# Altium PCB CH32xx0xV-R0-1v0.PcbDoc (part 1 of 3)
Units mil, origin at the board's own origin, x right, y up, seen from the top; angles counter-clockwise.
Board outline 3661.42 x 3267.72 mil, 2 copper layers (Top Layer, Bottom Layer); 68 components, 119 nets, 417 pads, 746 vias.
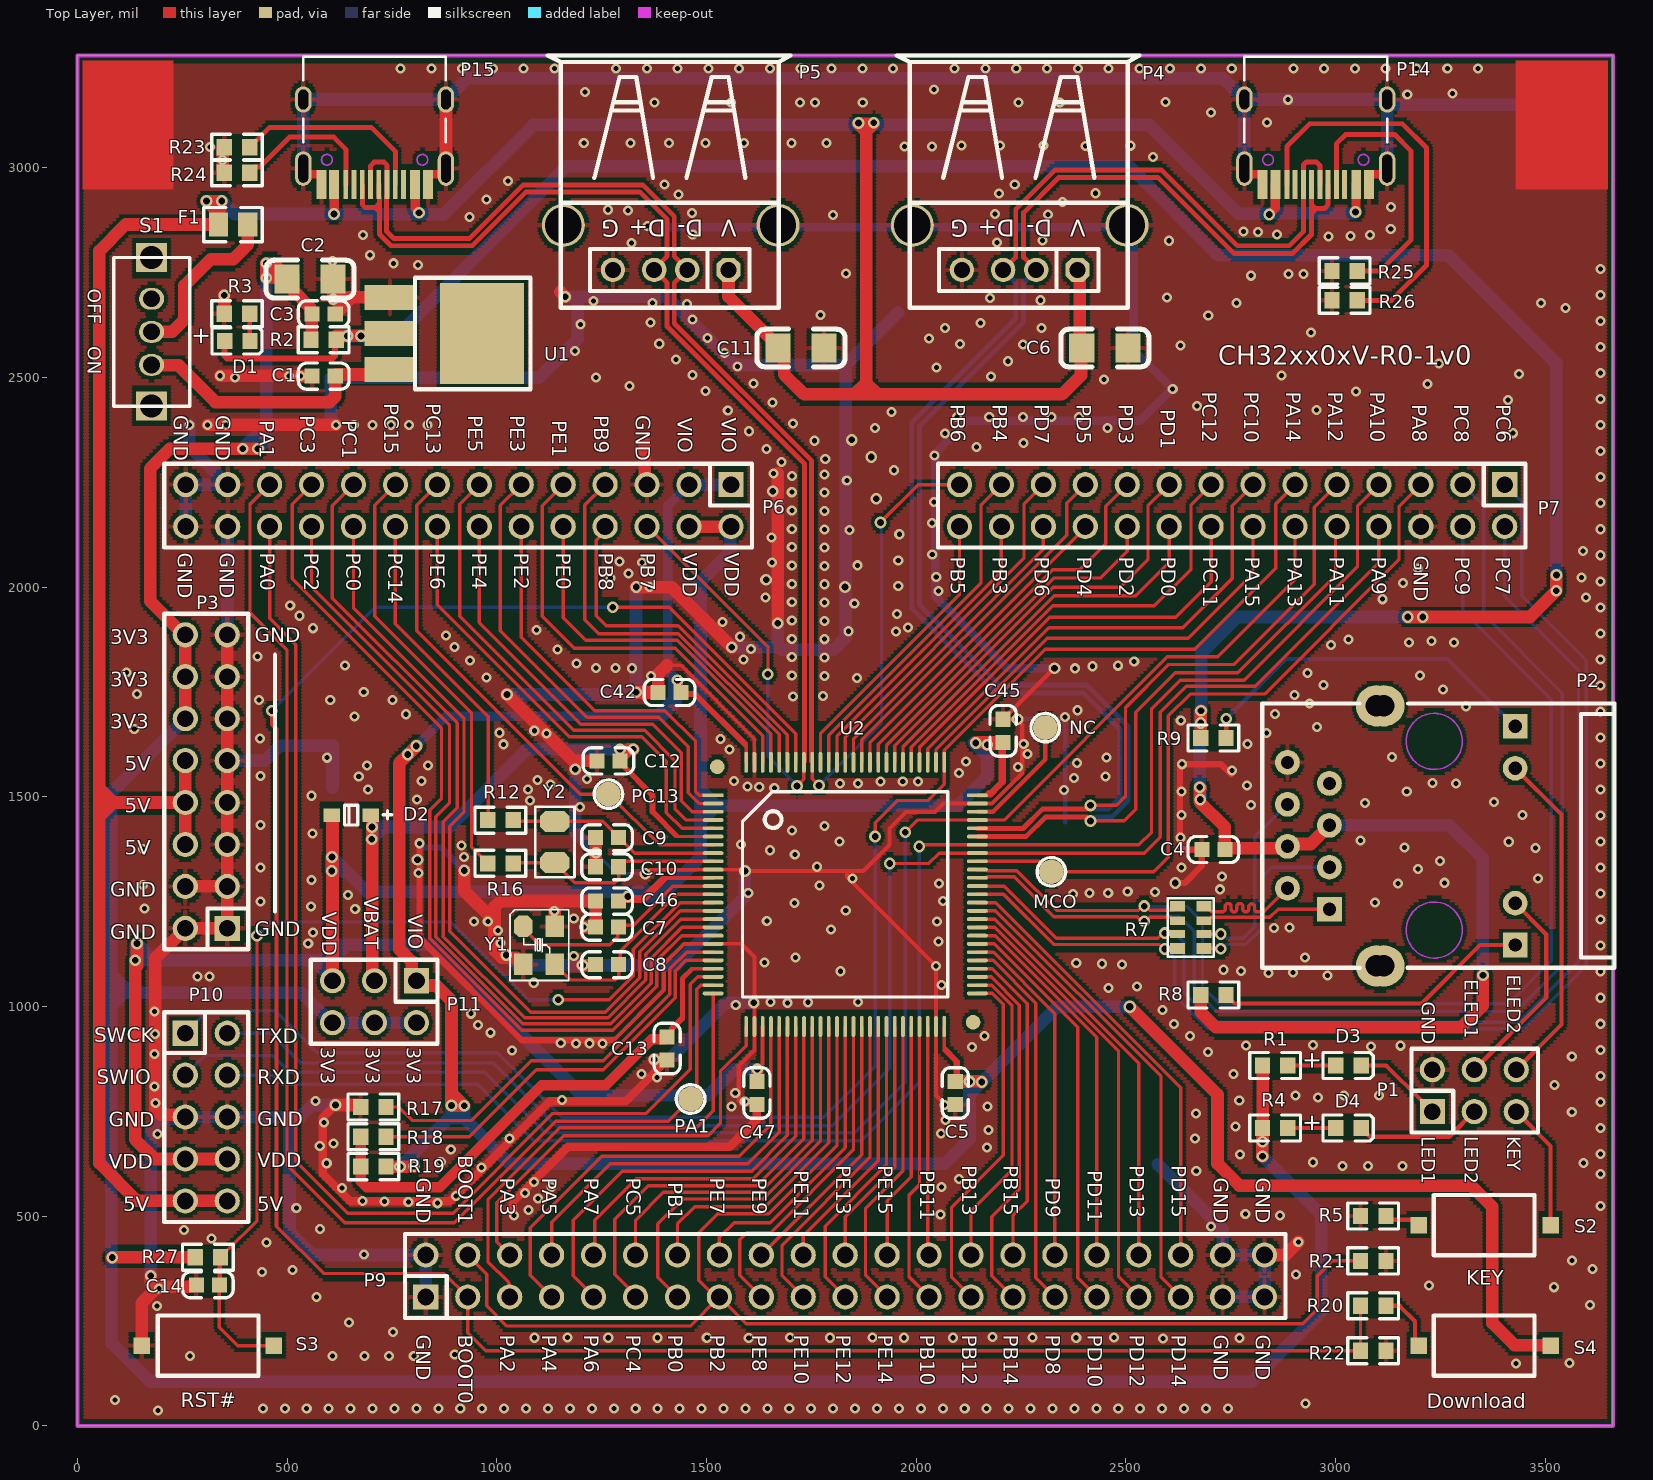
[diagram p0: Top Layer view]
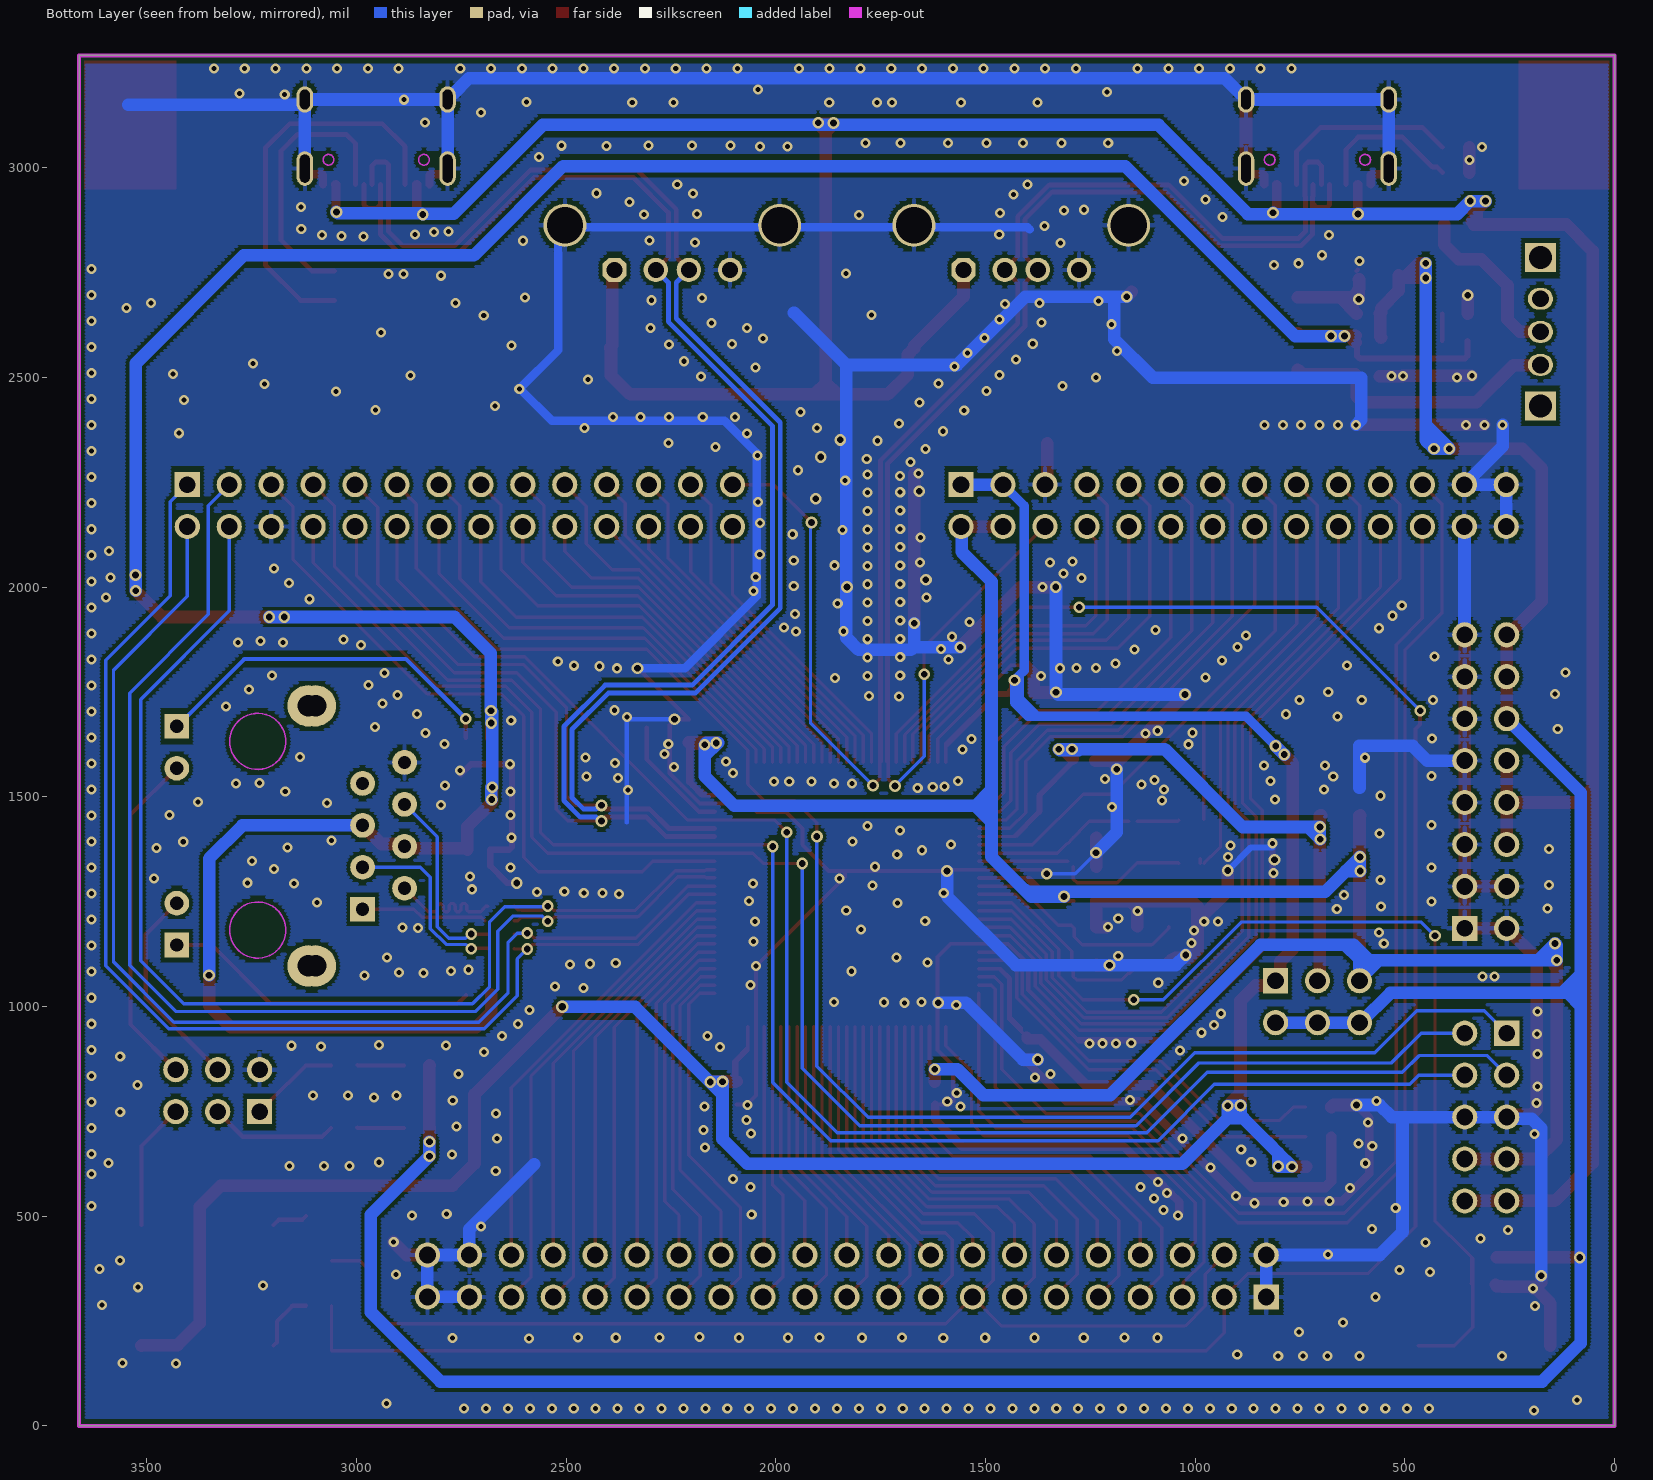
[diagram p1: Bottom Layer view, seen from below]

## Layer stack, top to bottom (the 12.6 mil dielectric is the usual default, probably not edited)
Top Solder: solder mask 0.4, Solder Resist, Dk 3.5
Top Layer: signal copper 1.4
Dielectric 1: dielectric 12.6, FR-4, Dk 4.8
Bottom Layer: signal copper 1.4
Bottom Solder: solder mask 0.4, Solder Resist, Dk 3.5

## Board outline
0,0 0,3267.72 3661.42,3267.72 3661.42,0

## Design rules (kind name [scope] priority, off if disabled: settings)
Clearance Clearance_1 [InPolygon] p1: gap=8 ignorepadtopadclearanceinfootprint=FALSE
Clearance [All] p2: gap=5 ignorepadtopadclearanceinfootprint=FALSE
ComponentClearance [All] p1 off: gap=10 collisioncheckmode=3 verticalgap=10 showdistances=FALSE
DiffPairsRouting [All] p1: maxlimit=10 minlimit=5 mostfreqgap=7 toplayer_minwidth=8 toplayer_maxwidth=15 toplayer_prefwidth=8 bottomlayer_minwidth=8 bottomlayer_maxwidth=15 bottomlayer_prefwidth=8 maxuncoupledlength=500
MinimumSolderMaskSliver [All] p1 off: minsoldermaskwidth=10
PolygonConnect PolygonConnect_1 [IsVia] p1: connectstyle=Direct reliefconductorwidth=10 reliefentries=4 polygonreliefangle="90 Angle" airgapwidth=10
PolygonConnect [All] p2: connectstyle=Relief reliefconductorwidth=10 reliefentries=4 polygonreliefangle="90 Angle" airgapwidth=10
RoutingVias [All] p1: holewidth=16 width=28 viastyle="Through Hole" minholewidth=12 minwidth=24 maxholewidth=28 maxwidth=50
SilkToSilkClearance [All] p1 off: silktosilkclearance=10
SilkToSolderMaskClearance [IsPad] p1 off: minsilkscreentomaskgap=10 clearancetoexposedcopper=TRUE
SolderMaskExpansion [All] p1: expansion=4 istentingtop=FALSE
Width [All] p1: maxlimit=100 minlimit=6 preferedwidth=10
25 further rules are at their usual default settings.

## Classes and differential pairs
differential pair ERX1: +ERXP1 -ERXN1

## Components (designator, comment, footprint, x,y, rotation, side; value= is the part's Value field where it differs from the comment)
C1 "0.1uF" 0603_C 614.71,2503.21 r180 top
C2 "10uF" 3216_C 499.71,2734.59 r180 top
C3 "0.1uF" 0603_C 559.72,2651.67 r0 top
C4 "1uF" 0603_C 2681.03,1374.36 r0 top
C5 "0.1uF" 0603_C 2093.21,821.36 r270 top
C6 "10uF" 3216_C 2394.73,2570.1 r180 top
C7 "22pF" 0603_C 1235.4,1189.11 r0 top
C8 "22pF" 0603_C 1235.4,1099.73 r0 top
C9 "12pF" 0603_C 1235.4,1402.61 r0 top
C10 "12pF" 0603_C 1235.4,1333.23 r0 top
C11 "10uF" 3216_C 1670.08,2570.1 r180 top
C12 "0.1uF" 0603_C 1238.69,1585.69 r0 top
C13 "0.1uF" 0603_C 1406.03,927.4 r270 top
C14 "0.1uF" 0603_C 283.44,336.36 r0 top
C42 "0.1uF" 0603_C 1384.49,1748.68 r0 top
C45 "0.1uF" 0603_C 2207.3,1629.96 r90 top
C46 "0.1uF" 0603_C 1290.39,1251.48 r180 top
C47 "0.1uF" 0603_C 1620.21,766.37 r90 top
D1 "RED" 0603+ 350.83,2586.93 r0 top
D2 "B0520WS" SOD-323 699.12,1456.36 r180 top
D3 "BLUE" 0603+ 3000.21,859.36 r0 top
D4 "RED" 0603+ 3000.21,710.36 r0 top
F1 "500mA" 0805 336.17,2864.6 r0 top
MCO "Testpoint" TESTPOINT1 2322.21,1321.36 r0 top
NC "Testpoint" TESTPOINT1 2307.69,1664.95 r0 top
P1 "IO" IDC6-2.54mm 3230.77,749.27 r0 top
P2 "HR911105A" HR911105A 2985.22,1231.99 r90 top
P3 "HEADER 8x2" IDC16-2.54mm 357.21,1186.36 r180 top
P4 "USBFS" USBAF 2384.59,2756.36 r180 top
P5 "USBHS" USBAF 1552.42,2756.36 r180 top
P6 "HEADER 14x2" IDC28-2.54MM 1558.21,2244.36 r270 top
P7 "HEADER 14x2" IDC28-2.54MM 3403.21,2244.36 r270 top
P9 "HEADER 21x2" IDC42-2.54MM 830.71,307.44 r90 top
P10 "LINK" IDC10-2.54mm 257.21,536.36 r0 top
P11 "HEADER 3x2" IDC6-2.54mm 808.21,1061.36 r180 top
P14 "USBFS" TYPE-C-Receptacle-2.0 2952.78,2959.96 r180 top
P15 "USBHS" TYPE-C-Receptacle-2.0 708.64,2959.96 r180 top
PA1 "Testpoint" TESTPOINT1 1462.18,779.41 r0 top
PC13 "Testpoint" TESTPOINT1 1266.21,1506.36 r0 top
R1 "1K" 0603 2825.58,859.36 r0 top
R2 "0R" 0603 556.9,2589.82 r0 top
R3 "1K" 0603 410.77,2651.66 r180 top
R4 "1K" 0603 2825.58,710.36 r0 top
R5 "10K" 0603 3059.47,500.58 r0 top
R7 "0Ω" RCA-8P4R-0603 2654.91,1188.5 r270 top
R8 "1K" 0603 2678.21,1027.36 r0 top
R9 "1K" 0603 2678.21,1640.36 r0 top
R12 "NC(0R)" 0603 978.21,1444.36 r0 top
R16 "NC(0R)" 0603 978.21,1341.36 r0 top
R17 "0R" 0603 675.15,760.26 r0 top
R18 "0R" 0603 675.15,689.26 r0 top
R19 "0R" 0603 735.78,618.26 r180 top
R20 "1K" 0603 3059.47,286.28 r0 top value=10K
R21 "10K" 0603 3059.47,393.43 r0 top
R22 "10K" 0603 3059.47,179.13 r0 top
R23 "NC(5.1K)" 0603 410.77,3048.82 r180 top
R24 "5.1K" 0603 410.77,2988 r180 top
R25 "5.1K" 0603 3051.97,2754.06 r180 top
R26 "5.1K" 0603 3051.97,2683.9 r180 top
R27 "10K" 0603 341.25,402.06 r180 top
S1 "SW SPDT" KEY2 176.66,2608.68 r90 top
S2 "KEY" SMD_6.1x3.65x2.5mm-KEY 3512.71,478.75 r180 top
S3 "RST#" SMD_6.1x3.65x2.5mm-KEY 153.21,191.36 r0 top
S4 "Download" SMD_6.1x3.65x2.5mm-KEY 3512.71,191.36 r180 top
U1 "1117-3.3V" SOT-223 744.97,2690.71 r270 top
U2 "CH32F207V" LQFP100 1515.75,1503.62 r270 top
Y1 "8MHz" XT3225 1063.21,1190.91 r270 top
Y2 "32768Hz" FC-135 1138.21,1441.36 r270 top

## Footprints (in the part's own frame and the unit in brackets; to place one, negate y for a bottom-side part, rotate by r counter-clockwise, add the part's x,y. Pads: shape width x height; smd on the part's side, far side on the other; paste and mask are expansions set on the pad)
0603 [mm]
  rect 0.93x0.98 smd: 1(0,0) 2(1.54,0)
  silkscreen extent -0.76,-0.79 2.3,0.79
0603+ [mm]
  rect 0.93x0.98 smd: 1(0,0) 2(1.54,0)
  silkscreen extent -0.76,-0.79 2.27,0.79
0603_C [mil]
  rect 36x36 smd: 1(0,0) 2(55,0)
  silkscreen extent -33,-31 88,31
0805 [mm]
  rect 1.16x1.47 smd: 1(0,0) 2(1.78,0)
  silkscreen extent -0.88,-1.04 2.66,1.03
3216_C [mil]
  rect 60x70 smd: 1(0,0) 2(-110,0)
  silkscreen extent -160,-45 50,45
FC-135 [mil]
  oct 50x70 smd: 1(0,0) 2(98.43,0)
  silkscreen extent -35,-47 133,47
HR911105A [mm]
  rect 1.5x1.5 hole 0.8: 1(0,0) 9(-2.175,-11.252) 12(11.075,-11.252)
  round 1.5 hole 0.8: 2(1.27,2.54) 3(2.54,0) 4(3.81,2.54) 5(5.08,0) 6(6.35,2.54) 7(7.62,0) 8(8.89,2.54) 10(0.365,-11.252) 11(8.535,-11.252)
  round 2.5 hole 1.3: ""(-3.43,-2.852) ""(-3.43,-3.3) ""(12.32,-3.3) ""(12.32,-2.852)
  Keep-Out Layer circle w0.1: c10.165,-6.352 r1.7
  Keep-Out Layer circle w0.1: c-1.265,-6.352 r1.7
  silkscreen extent -3.55,-17.27 12.45,4.06
IDC6-2.54mm [mil]
  rect 60x60 hole 40: 1(0,0)
  round 60 hole 40: 2(0,100) 3(100,0) 4(100,100) 5(200,0) 6(200,100)
  silkscreen extent -50,-50 252,150
IDC10-2.54mm [mil]
  rect 60x60 hole 40: 1(0,400)
  round 60 hole 40: 2(100,400) 3(0,300) 4(100,300) 5(0,200) 6(100,200) 7(0,100) 8(100,100) 9(0,0) 10(100,0)
  silkscreen extent -50,-50 150,450
IDC16-2.54mm [mil]
  rect 60x60 hole 40: 1(0,0)
  round 60 hole 40: 2(100,0) 3(0,-100) 4(100,-100) 5(0,-200) 6(100,-200) 7(0,-300) 8(100,-300) 9(0,-400) 10(100,-400) 11(0,-500) 12(100,-500) 13(0,-600) 14(100,-600) 15(0,-700) 16(100,-700)
  silkscreen extent -50,-750 150,50
IDC28-2.54MM [mil]
  rect 60x60 hole 40: 1(0,0)
  round 60 hole 40: 2(100,0) 3(0,-100) 4(100,-100) 5(0,-200) 6(100,-200) 7(0,-300) 8(100,-300) 9(0,-400) 10(100,-400) 11(0,-500) 12(100,-500) 13(0,-600) 14(100,-600) 15(0,-700) 16(100,-700) 17(0,-800) 18(100,-800) 19(0,-900) 20(100,-900) 21(0,-1000) 22(100,-1000) 23(0,-1100) 24(100,-1100) 25(0,-1200) 26(100,-1200) 27(0,-1300) 28(100,-1300)
  silkscreen extent -50,-1351 150,50
IDC42-2.54MM [mil]
  rect 60x60 hole 40: 1(0,0)
  round 60 hole 40: 2(100,0) 3(0,-100) 4(100,-100) 5(0,-200) 6(100,-200) 7(0,-300) 8(100,-300) 9(0,-400) 10(100,-400) 11(0,-500) 12(100,-500) 13(0,-600) 14(100,-600) 15(0,-700) 16(100,-700) 17(0,-800) 18(100,-800) 19(0,-900) 20(100,-900) 21(0,-1000) 22(100,-1000) 23(0,-1100) 24(100,-1100) 25(0,-1200) 26(100,-1200) 27(0,-1300) 28(100,-1300) 29(0,-1400) 30(100,-1400) 31(0,-1500) 32(100,-1500) 33(0,-1600) 34(100,-1600) 35(0,-1700) 36(100,-1700) 37(0,-1800) 38(100,-1800) 39(0,-1900) 40(100,-1900) 41(0,-2000) 42(100,-2000)
  silkscreen extent -50,-2050 150,50
KEY2 [mm]
  rect 1.75x1.9 hole 1.4: 0(-4.5,0) 0(4.5,0)
  oval 1.321x1.524 hole 1.016: 1(0,0) 2(-2,0) 3(2,0)
  silkscreen extent -4.51,-2.31 4.5,2.29
LQFP100 [mil]
  round 35 smd: 0(-68,10) 0(541.18,620)
  rect 9x50 smd: 1(0,0)
  oval 9x50 smd: 2(19.68,0) 3(39.37,0) 4(59.05,0) 5(78.74,0) 6(98.42,0) 7(118.11,0) 8(137.79,0) 9(157.48,0) 10(177.16,0) 11(196.85,0) 12(216.53,0) 13(236.22,0) 14(255.9,0) 15(275.59,0) 16(295.27,0) 17(314.96,0) 18(334.64,0) 19(354.33,0) 20(374.01,0) 21(393.7,0) 22(413.38,0) 23(433.07,0) 24(452.75,0) 25(472.44,0) 51(472.44,629.92) 52(452.75,629.92) 53(433.07,629.92) 54(413.38,629.92) 55(393.7,629.92) 56(374.01,629.92) 57(354.33,629.92) 58(334.64,629.92) 59(314.96,629.92) 60(295.27,629.92) 61(275.59,629.92) 62(255.9,629.92) 63(236.22,629.92) 64(216.53,629.92) 65(196.85,629.92) 66(177.16,629.92) 67(157.48,629.92) 68(137.79,629.92) 69(118.11,629.92) 70(98.42,629.92) 71(78.74,629.92) 72(59.05,629.92) 73(39.37,629.92) 74(19.68,629.92) 75(0,629.92)
  oval 50x9 smd: 26(551.18,78.74) 27(551.18,98.43) 28(551.18,118.11) 29(551.18,137.8) 30(551.18,157.48) 31(551.18,177.17) 32(551.18,196.85) 33(551.18,216.54) 34(551.18,236.22) 35(551.18,255.91) 36(551.18,275.59) 37(551.18,295.28) 38(551.18,314.96) 39(551.18,334.65) 40(551.18,354.33) 41(551.18,374.02) 42(551.18,393.7) 43(551.18,413.39) 44(551.18,433.07) 45(551.18,452.76) 46(551.18,472.44) 47(551.18,492.13) 48(551.18,511.81) 49(551.18,531.5) 50(551.18,551.18) 76(-78.74,551.18) 77(-78.74,531.5) 78(-78.74,511.81) 79(-78.74,492.13) 80(-78.74,472.44) 81(-78.74,452.76) 82(-78.74,433.07) 83(-78.74,413.39) 84(-78.74,393.7) 85(-78.74,374.02) 86(-78.74,354.33) 87(-78.74,334.65) 88(-78.74,314.96) 89(-78.74,295.28) 90(-78.74,275.59) 91(-78.74,255.91) 92(-78.74,236.22) 93(-78.74,216.54) 94(-78.74,196.85) 95(-78.74,177.17) 96(-78.74,157.48) 97(-78.74,137.8) 98(-78.74,118.11) 99(-78.74,98.43) 100(-78.74,78.74)
  silkscreen extent -8,70 481,560
RCA-8P4R-0603 [mm]
  rect 0.65x0.9 smd: 1(-1.28,-0.8) 4(1.28,-0.8) 5(1.28,0.8) 8(-1.28,0.8)
  rect 0.5x0.9 smd: 2(-0.4,-0.8) 3(0.4,-0.8) 6(0.4,0.8) 7(-0.4,0.8)
  silkscreen extent -1.78,-1.4 1.78,1.4, body extent -1.6,-0.8 1.6,0.8, height 0.6
SMD_6.1x3.65x2.5mm-KEY [mm]
  rect 1x1 smd: 1(0,0) 2(8,0)
  silkscreen extent 0.98,-1.83 7.08,1.83
SOD-323 [mm]
  rect 1x0.83 smd: 1(0,0) 2(2.36,0)
  silkscreen extent -1.28,-0.6 1.58,0.6
SOT-223 [mil]
  rect 60x120 smd: 1(0,0) 2(86,0) 3(172,0)
  rect 240x200 smd: ""(86,220)
  silkscreen extent -47,60 219,335
TESTPOINT1 [mm]
  round 1.5 smd: 1(0,0)
  silkscreen extent -0.86,-0.86 0.87,0.86
TYPE-C-Receptacle-2.0 [mm]
  oval 1x2.1 hole 0.6 slot 1.7 at 90 deg: 0(-4.32,-0.97) 0(4.32,-0.97)
  oval 1x1.6 hole 0.6 slot 1.2 at 90 deg: 0(-4.32,-5.15) 0(4.32,-5.15)
  rect 0.6x1.75 smd: A1(-3.225,0) A4(-2.45,0) B1(3.225,0) B4(2.45,0)
  rect 0.3x1.75 smd: A5(-1.25,0) A6(-0.25,0) A7(0.25,0) A8(1.25,0) B5(1.75,0) B6(0.75,0) B7(-0.75,0) B8(-1.75,0)
  Keep-Out Layer circle w0.1: c2.89,-1.5 r0.325
  Keep-Out Layer circle w0.1: c-2.89,-1.5 r0.325
  silkscreen extent -4.32,-7.75 4.32,-2.55
USBAF [mm]
  round 2.6 hole 2.2: 0(-3,-2.7) 0(10,-2.7)
  oct 1.473x1.473 hole 0.965: 1(0,0)
  round 1.473 hole 0.965: 2(2.5,0) 3(4.5,0) 4(7,0)
  silkscreen extent -3.75,-12.99 10.95,2.29
XT3225 [mm]
  oct 1.3x1.1 smd: 1(0,0)
  rect 1.3x1.1 smd: 2(2.3,0) 3(2.3,1.9) 4(0,1.9)
  silkscreen extent -1.02,-0.8 3.27,2.74

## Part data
C1 C2 C3 C4 C5 C6 C7 C8 C9 C10 C12 C13 C14 C42 C45 C46 C47: library part CAP, "Capacitor"
C11: library part Cap, "Capacitor"
D1 D3 D4: library part LED0, "Typical INFRARED GaAs LED"
D2: library part DIODE, "Diode"
F1: library part FUSE1, "Fuse"
MCO NC PA1 PC13: "测试点"
P1: library part "HEADER 3x2", "Header, 3-Pin, Dual row"
P2: library part "Header 7X2", "Header, 7-Pin, Dual row"
P3: "Header, 8-Pin, Dual row"
P4 P5: library part USB, "USB Port"
P6 P7: "Header, 14-Pin, Dual row"
P9: "Header, 21-Pin, Dual row"
P10: library part "HEADER 5x2", "Header, 5-Pin, Dual row"
P11: "Header, 3-Pin, Dual row"
P14 P15: library part TYPE-C1
R1 R2 R3 R4 R5 R8 R9 R12 R16: library part RES
R7: library part R-8P4R, "贴片网络排阻"
R17 R18 R19: library part R
R20 R21 R22 R23 R24 R25 R26 R27: library part Res2, "Resistor"
S2 S3 S4: library part KEY1
U2: library part CH32V303V, "RISC-V FPU HD-MCU, 144MHz, 8*UART, 10*Timer, 4*OPA"
Y1 Y2: library part XTAL, "Crystal Oscillator"

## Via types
v1: diameter 24, hole 12, Top Layer to Bottom Layer, tented both sides, 648 vias
v2: diameter 28, hole 16, Top Layer to Bottom Layer, tented both sides, 97 vias
v3: diameter 30, hole 18, Top Layer to Bottom Layer, tented both sides, 1 vias

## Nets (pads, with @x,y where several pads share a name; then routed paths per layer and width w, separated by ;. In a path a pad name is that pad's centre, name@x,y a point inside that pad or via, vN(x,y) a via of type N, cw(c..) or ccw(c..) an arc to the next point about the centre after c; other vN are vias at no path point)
3V3: C2.1 C3.1 P3.12 P3.14 P3.16 P11.2 P11.4 P11.6 R1.1 R2.1 R4.1 R27.2 | length 8243.8
  Top Layer w30: v2@82.44,401.29 v2(82.83,401.67) 83.22,402.06 R27.2@280.62,402.06 ; P3.12@257.21,1686.36 P3.14@257.21,1786.36 P3.16@257.21,1886.36 253.57,1886.36 173.21,1966.72 173.21,2282.74 220.61,2330.14 v2(394.05,2330.14) v2(430.45,2330.14) ; R2.1@556.9,2595.24 558.31,2596.65 C3.1@558.31,2651.67 ; C3.1@559.72,2651.67 556.72,2654.67 556.72,2664.74 514.71,2706.76 514.71,2744.1 507.93,2737.32 C2.1@501.98,2737.32 ; R4.1@2825.58,710.36 2825.58,643.45 v2(2825.96,643.07) ; R1.1@2825.58,859.36 2825.96,858.98 v2(2825.96,677.55) ; 450.18,2757.89 C2.1@481.41,2757.89 ; 450.18,2757.89 v2(450.18,2772.54) 466.76,2772.54 C2.1@481.41,2757.89 ; 450.18,2757.89 450.18,2737.39 v2(450.1,2737.32) C2.1@501.98,2737.32 ; C2.1@481.41,2757.89 C2.1@501.98,2737.32
  Bottom Layer w30: 119.54,1032.34 124.99,1032.34 ; P3.12@257.21,1686.36 80.94,1510.09 80.94,1076.39 ; v2(450.1,2737.32) v2@450.18,2737.39 ; 450.18,2426.39 450.18,2386.27 ; v2(450.18,2772.54) v2@450.18,2737.39 ; P11.2@808.21,961.36 P11.4@708.21,961.36 P11.6@608.21,961.36 605.59,961.36 534.61,1032.34 124.99,1032.34 ; v2(2825.96,677.55) v2(2825.96,643.07) 2965.37,503.67 2965.37,270.92 2799.98,105.53 172.78,105.53 80.94,197.36 80.94,1001.74 ; 80.94,1001.74 111.54,1032.34 87.67,1032.34 80.94,1039.07 ; 80.94,1001.74 80.94,1039.07 ; 80.94,1039.07 80.94,1076.39 ; 80.94,1076.39 124.99,1032.34 ; v2@434.44,2334.13 450.18,2349.87 450.18,2386.27 ; v2@434.44,2334.13 434.44,2370.53 ; v2@434.44,2334.13 v2(430.45,2330.14) v2(394.05,2330.14) 434.44,2370.53 ; 434.44,2370.53 450.18,2386.27 ; 450.18,2386.27 v2@450.18,2737.39
3V3S: C4.2 D1.1 P2.4 P2.5 R2.2 R8.1 R9.1 U1.2 | length 7702.8
  Top Layer w15: D1.1@350.83,2586.93 350.83,2551.77 357.42,2545.17 607.37,2545.17 613.96,2551.77 613.96,2586.25 R2.2@617.53,2589.82
  Top Layer w30: R2.2@617.53,2583.72 R2.2@633.34,2599.53 ; R2.2@617.6,2599.53 749.79,2599.53 U1.2@754.97,2604.71 ; R8.1@2678.21,1027.36 2678.21,986.5 2714.46,950.25 3299.11,950.25 3351.28,1002.43 v2(3351.28,1074.7) ; v2@2678.21,1520.45 v2(2675.88,1522.78) 2675.88,1488.09 2736.03,1427.94 2736.03,1377.17 C4.2@2737.44,1375.76 ; v2(2678.43,1675.92) 2678.43,1640.58 R9.1@2678.21,1640.36 2678.21,1704.2 v2(2679.34,1705.33) ; C4.2@2736.03,1374.36 C4.2@2737.44,1375.76 ; P2.5@2985.22,1431.99 2940.78,1387.55 2890.78,1387.55 P2.4@2885.22,1381.99 2880.59,1377.36 2739.03,1377.36 C4.2@2737.44,1375.76 ; v2(3172.22,1928.7) 3172.33,1928.81 v2(3207.99,1928.81) 3463.62,1928.81 v2(3526.06,1991.24) 3526.56,1991.74 v2(3526.56,2028.8)
  Bottom Layer w30: v2(644.16,2598.65) 675.97,2598.65 761.88,2598.65 1166.91,3003.68 2507.19,3003.68 2719.76,2791.11 3268.76,2791.11 3526.06,2533.81 3526.06,2028.8 v2(3526.06,1991.24) ; v2(2675.88,1522.78) 2675.88,1702.77 2678.43,1705.33 v2(2678.43,1675.92) ; v2(2677.44,1493.83) 2678.43,1494.82 v2@2678.43,1522.78 ; v2(2679.34,1705.33) 2679.34,1842.03 2766.12,1928.81 v2(3207.99,1928.81) ; P2.5@2985.22,1431.99 3271.87,1431.99 3351.28,1352.58 3351.28,1079.77 v2(3351.28,1074.7)
  other v2: 675.97,2598.71
5V: C6.1 C11.1 F1.1 P3.6 P3.8 P3.10 P4.1 P5.1 P10.9 P10.10 P14.A4 P14.B4 P15.A4 P15.B4 | length 8780.7
  Top Layer w22: v2(611.88,2889.69) 612.19,2890 P15.B4@612.19,2959.96 P15.B4@612.49,2960.27 ; P15.A4@805.41,2960.27 805.41,2903.19 814.2,2894.4 v2(814.2,2892.78) ; v2(2841.64,2888.68) 2841.64,2888.83 2856.32,2903.51 P14.B4@2856.32,2959.96 ; v2(3047.72,2894.55) 3048.48,2895.3 3048.48,2959.2 P14.A4@3049.23,2959.96
  Top Layer w30: P3.6@257.21,1386.36 P3.8@257.21,1486.36 ; P3.10@257.21,1586.36 P3.8@257.21,1486.36 ; F1.1@336.17,2864.6 F1.1@334.12,2866.65 ; F1.1@339.9,2872.43 F1.1@334.12,2866.65 ; 339.9,2900.19 339.9,2916.27 v2(344.23,2920.6) v2(307.71,2920.6) 328.12,2900.19 328.12,2884.38 328.33,2884.17 328.33,2872.43 F1.1@334.12,2866.65 ; P10.10@357.21,536.36 P10.9@257.21,536.36 142.44,536.36 52.11,626.68 52.11,1453.05 ; P5.1@1552.42,2756.36 1552.42,2692.76 1670.08,2575.1 C11.1@1670.08,2570.1 1685.08,2555.1 1685.08,2507.5 1732.68,2459.9 1853.5,2459.9 ; v2@1898.89,3105.16 v2@1898.18,3104.45 ; 1907.5,2459.49 2347.34,2459.49 2392.94,2505.1 C6.1@2392.94,2571.88 ; P4.1@2384.59,2756.36 2389.66,2751.29 2389.66,2575.17 C6.1@2392.94,2571.88 ; C6.1@2394.73,2570.1 C6.1@2392.94,2571.88 ; 52.11,1453.05 52.11,1486.36 ; 52.11,1453.05 85.43,1486.36 ; 52.11,1486.36 52.11,1519.67 ; 52.11,1486.36 85.43,1486.36 ; 52.11,1519.67 52.11,2801.69 115.02,2864.6 332.07,2864.6 F1.1@334.12,2866.65 ; 52.11,1519.67 85.43,1486.36 ; 85.43,1486.36 P3.8@257.21,1486.36 ; 1853.5,2459.9 1880.5,2459.9 ; 1853.5,2459.9 1880.5,2486.9 ; 1880.5,2459.9 1907.5,2459.9 1880.5,2486.9 ; 1880.5,2459.9 1880.5,2486.9 ; 1880.5,2486.9 1880.5,3086.38 ; 1880.5,3086.38 1862.43,3104.45 v2@1898.18,3104.45 ; 1880.5,3086.38 1880.5,3086.77 v2@1898.18,3104.45
  Bottom Layer w30: v2(307.71,2920.6) v2(344.23,2920.6) 375.13,2889.69 v2(611.88,2889.69) ; v2@611.88,2889.38 v2@817.59,2889.38 ; v2(814.2,2892.78) v2@817.59,2889.38 ; v2(3047.72,2894.55) 3044.62,2891.44 2844.4,2891.44 v2(2841.64,2888.68) 2840.26,2890.06 2768.06,2890.06 2555.69,3102.43 1898.89,3102.43 1862.43,3102.43 1087.31,3102.43 874.26,2889.38 v2@817.59,2889.38
  other v2: 1862.43,3106.45 1898.89,3107.16
BOOT0: P9.3 R20.1 R22.1 U2.94 | length 5642.6
  Top Layer w8: 474.62,476.52 587.95,363.18 874.96,363.18 P9.3@930.71,307.44 930.71,222.15 973.73,179.13 R22.1@3059.47,179.13 R20.1@3059.47,286.28 ; v2(1276.44,1951.92) 1411.5,1951.92 1712.6,1650.83 U2.94@1712.6,1582.36
  Top Layer w10: v2(463.62,1704.96) 463.62,1672.83 474.62,1661.83 474.62,476.52
  Bottom Layer w8: v2(463.62,1704.96) 710.58,1951.92 v2(1276.44,1951.92)
BOOT1: P9.4 P9.15 R21.1 U2.37 | length 3285.4
  Top Layer w8: P9.4@930.71,407.44 976.2,361.95 976.2,286.06 1024.23,238.03 1461.3,238.03 P9.15@1530.71,307.44 ; U2.37@1811.02,952.44 1811.02,668.2 1648.33,505.5 1526.57,505.5 1481.64,460.57 1481.64,346.9 1521.1,307.44 P9.15@1530.71,307.44 ; R21.1@3059.47,393.43 2991.94,393.43 2955.89,357.37 2955.89,278.55 2921.16,243.83 1594.32,243.83 P9.15@1530.71,307.44
ELED1: P1.4 P2.10 | length 498.7
  Top Layer w10: P1.4@3330.77,849.27 3502.21,1020.72 3502.21,1172.36 P2.10@3428.21,1246.36
ELED2: P1.6 P2.11 | length 954.4
  Top Layer w10: P2.11@3428.21,1568.01 3538.74,1457.49 3538.74,957.24 ; P1.6@3430.77,849.27 3538.74,957.24 ; 3538.74,1102.4 3538.74,957.24
ERXN: P7.2 R7.3 U2.64 | length 2846.9
  Top Layer w8: U2.64@2145.67,1287.08 2209.9,1287.08 2334.05,1162.93 2576.38,1162.93 2586.21,1172.75 R7.3@2623.41,1172.75
  Bottom Layer w8: v2@2594.51,1175.01 2616.93,1175.01 2638.46,1153.48 2638.46,1032.46 2708.2,962.72 3435.04,962.72 3579.26,1106.94 3579.26,1802.18 3403.21,1978.24 P7.2@3403.21,2144.36
  other v2: 2592.81,1175.01
ERXN1: P2.6 R7.6 | length 460.3
  Top Layer w8: R7.6@2686.41,1172.75 2687.23,1171.93 v2@2726.37,1171.93
  Bottom Layer w8: v2@2726.37,1171.93 2730.88,1171.93 2739.88,1162.93 2779.97,1162.93 2807.49,1190.44 2807.49,1404.26 P2.6@2885.22,1481.99
  other v2: 2726.37,1172.93
ERXP: P7.1 R7.4 U2.63 | length 2957.4
  Top Layer w8: U2.63@2145.67,1267.4 2208.16,1267.4 2327.63,1147.93 2579.29,1147.93 2587.25,1139.97 2599.23,1139.97 2602.05,1137.16 2622.47,1137.16 R7.4@2623.41,1138.1
  Bottom Layer w8: v2(2592.81,1137.16) 2616.65,1113.32 2616.65,1025.27 2695.12,946.8 3447.34,946.8 3597.64,1097.11 3597.64,1825.66 3443.95,1979.35 3443.95,2203.62 P7.1@3403.21,2244.36
ERXP1: P2.3 R7.5 | length 451.1
  Top Layer w8: R7.5@2686.41,1138.1 2687.23,1138.93 v2@2726.37,1138.93
  Bottom Layer w8: v2@2726.37,1138.93 2730.88,1138.93 2739.88,1147.93 2786.19,1147.93 2823.75,1185.49 2823.75,1308.33 2847.41,1331.99 P2.3@2985.22,1331.99
  other v2: 2726.37,1137.93
ETXN: P7.4 R7.1 U2.66 | length 2854.2
  Top Layer w8: U2.66@2145.67,1326.45 2166.44,1326.45 2168.78,1324.11 2239.6,1324.11 2334.64,1229.07 2530.02,1229.07 2540.33,1239.38 2547.2,1239.38 2557.05,1229.53 2606.18,1229.53 2606.75,1230.1 2614.62,1230.1 R7.1@2623.41,1238.89
  Bottom Layer w8: v2(2543.53,1239.38) 2544.64,1238.27 2646.31,1238.27 2682.57,1202.01 2682.57,1046.8 2723.2,1006.16 3411.42,1006.16 3514.55,1109.3 3514.55,1732.04 3303.21,1943.39 P7.4@3303.21,2144.36
ETXN1: P2.2 R7.8 | length 310.2
  Top Layer w8: R7.8@2686.41,1238.89 2691.33,1238.89 2700.12,1230.1 2700.12,1229.26 2703.64,1225.74 2725.75,1225.74 2729.75,1225.74 ccw(c2729.75,1232.74) 2736.75,1232.74 2736.75,1238.74 cw(c2743.75,1238.74) 2750.75,1238.74 2750.75,1232.7 ccw(c2757.75,1232.7) 2764.75,1232.7 2764.75,1238.74 cw(c2771.75,1238.74) 2778.75,1238.74 2778.75,1232.7 ccw(c2785.75,1232.7) 2792.75,1232.7 2792.75,1237.76 cw(c2799.75,1237.76) 2806.75,1237.76 2806.75,1232.74 ccw(c2813.75,1232.74) 2813.75,1225.74 2828.97,1225.74 P2.2@2885.22,1281.99
ETXP: P7.3 R7.2 U2.65 | length 2998.6
  Top Layer w8: U2.65@2145.67,1306.77 2166.44,1306.77 2168.78,1309.11 2233.39,1309.11 2328.43,1214.07 2527.31,1214.07 2538.34,1203.04 2547.09,1203.04 2557.26,1213.21 2606.57,1213.21 2615.54,1204.25 R7.2@2623.41,1204.25
  Bottom Layer w8: v2(2543.75,1203.04) 2544.59,1203.04 2557.24,1215.7 2626.93,1215.7 2663.07,1179.56 2663.07,1040.92 2715.87,988.12 3430.94,988.12 3540.71,1097.89 3540.71,1747.17 3353.11,1934.77 3353.11,2194.46 P7.3@3303.21,2244.36
ETXP1: P2.1 R7.7 | length 302.4
  Top Layer w8: R7.7@2694.28,1204.25 2702.73,1212.7 2843.45,1212.7 2862.74,1231.99 P2.1@2985.22,1231.99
